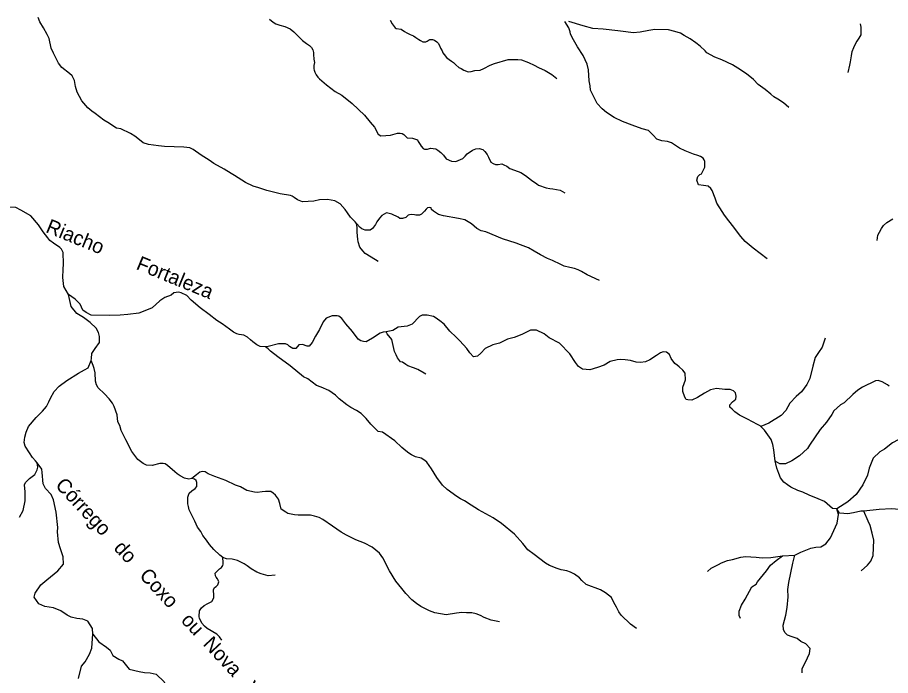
# Model space of a CAD drawing. Extents: x 717.8 to 772.7, y 8672.2 to 8728.
# Drawn here: x 733.27 to 745.36, y 8718.74 to 8727.85 of the extents above; entities that cross this region are included whole.
import ezdxf
from ezdxf.enums import TextEntityAlignment as Align

# ---------------------------------------------------------------- set-up
doc = ezdxf.new("R2010")
doc.units = 0
doc.header["$LTSCALE"] = 0.08
doc.linetypes.add('LONG_DASHED', pattern=[7.5, 6, -1.5])
doc.layers.add('61', color=7, linetype='Continuous')
doc.layers.add('9', color=7, linetype='LONG_DASHED', lineweight=25)

msp = doc.modelspace()

# ---------------------------------------------------------------- linework, layer by layer
at = {"layer": '9'}
for p, q in [((738.4321, 8727.8129), (738.462, 8727.7588)), ((743.8674, 8720.3918), (744.0397, 8720.4031))]:
    msp.add_line(p, q, dxfattribs=at)
for points in [[(737.9695, 8724.9957), (737.9482, 8725.0169), (737.885, 8725.0835), (737.8439, 8725.1443), (737.8126, 8725.192), (737.7401, 8725.2678), (737.6689, 8725.3118), (737.567, 8725.3298), (737.4566, 8725.3222), (737.3782, 8725.3061), (737.2182, 8725.2979), (737.1508, 8725.3221), (737.1055, 8725.3559), (737.0754, 8725.3727), (737.0554, 8725.3822), (736.91, 8725.4073), (736.7243, 8725.4523), (736.6139, 8725.4875), (736.5356, 8725.5139), (736.4314, 8725.5614), (736.2793, 8725.6596), (736.2341, 8725.6896), (736.1335, 8725.7497), (735.993, 8725.8287), (735.9293, 8725.8715), (735.8152, 8725.9428), (735.7068, 8726.0199), (735.6588, 8726.0425), (735.5783, 8726.0535), (735.3079, 8726.061), (735.2274, 8726.0705), (735.155, 8726.0821), (735.0896, 8726.0896), (735.0131, 8726.1134), (734.9419, 8726.173), (734.9002, 8726.2037), (734.8372, 8726.2428), (734.7058, 8726.3082), (734.6444, 8726.3175), (734.5245, 8726.3945), (734.4678, 8726.4283), (734.3509, 8726.517), (734.3017, 8726.55), (734.2478, 8726.5986), (734.1656, 8726.6926), (734.1007, 8726.8137), (734.077, 8726.8954), (734.0634, 8726.974), (734.0287, 8727.0409), (733.9942, 8727.0731), (733.8894, 8727.1578), (733.8407, 8727.218), (733.773, 8727.3538), (733.7412, 8727.4227), (733.714, 8727.5577), (733.6826, 8727.6141), (733.6351, 8727.705), (733.5819, 8727.7902), (733.5604, 8727.8492)], [(736.7653, 8727.8257), (736.8126, 8727.7819), (736.8493, 8727.7589), (736.9078, 8727.7417), (736.9741, 8727.7222), (737.0486, 8727.6909), (737.0982, 8727.648), (737.2215, 8727.5289)], [(738.462, 8727.7588), (738.5015, 8727.7078), (738.518, 8727.6957), (738.5874, 8727.6855), (738.6313, 8727.6541), (738.664, 8727.6384), (738.7115, 8727.6142), (738.7578, 8727.5925), (738.7905, 8727.5719), (738.8293, 8727.5442), (738.8554, 8727.5296), (738.8879, 8727.5105), (738.929, 8727.5095), (738.9483, 8727.5218), (738.9751, 8727.541), (738.9851, 8727.5428)], [(743.6572, 8724.5082), (743.4593, 8724.652), (743.3516, 8724.7475), (743.2897, 8724.8172), (743.2452, 8724.874), (743.195, 8724.9443), (743.1246, 8725.0317), (743.0628, 8725.1129), (743.0331, 8725.1626), (742.957, 8725.2755), (742.9331, 8725.3482), (742.8925, 8725.454), (742.8738, 8725.4798), (742.8358, 8725.5134), (742.7719, 8725.5216), (742.7026, 8725.5325), (742.6804, 8725.5971), (742.6971, 8725.6487), (742.7236, 8725.6726), (742.7455, 8725.6835), (742.7917, 8725.7782), (742.7921, 8725.8528), (742.7843, 8725.8795), (742.7702, 8725.8992), (742.7331, 8725.9221), (742.6946, 8725.9398), (742.6346, 8725.954), (742.5181, 8726.0009), (742.4391, 8726.0378), (742.33, 8726.1137), (742.2769, 8726.1295), (742.1957, 8726.14), (742.1293, 8726.1616), (742.0777, 8726.217), (742.0113, 8726.2828), (741.9244, 8726.3067), (741.7863, 8726.3583), (741.652, 8726.4073), (741.5347, 8726.4656), (741.4324, 8726.5339), (741.3686, 8726.5845), (741.3022, 8726.6577), (741.2511, 8726.7578), (741.2085, 8726.8433), (741.2048, 8726.9023), (741.1911, 8726.9713), (741.1827, 8727.1257), (741.1642, 8727.2042), (741.1057, 8727.3222), (741.0277, 8727.4433), (740.9723, 8727.5375), (740.9326, 8727.6158), (740.9276, 8727.6488), (740.9087, 8727.7054), (740.8522, 8727.7945)], [(743.9561, 8726.6007), (743.8791, 8726.6681), (743.8029, 8726.7154), (743.7468, 8726.7491), (743.7067, 8726.7868), (743.6256, 8726.8495), (743.5303, 8726.9216), (743.4643, 8726.9898), (743.3673, 8727.0685), (743.2478, 8727.1447), (743.1748, 8727.1929), (743.028, 8727.2611), (742.9285, 8727.2972), (742.8202, 8727.3582), (742.7978, 8727.3879), (742.729, 8727.4505), (742.6672, 8727.4994), (742.5878, 8727.5548), (742.5059, 8727.6014), (742.4554, 8727.6311), (742.3784, 8727.656), (742.291, 8727.6792), (742.0984, 8727.6817), (742.015, 8727.6677), (741.8946, 8727.6439), (741.7983, 8727.6375), (741.6957, 8727.6479), (741.5874, 8727.6656), (741.382, 8727.6872), (741.2395, 8727.6985), (741.1084, 8727.7312), (740.9085, 8727.7939)], [(744.7759, 8727.086), (744.7988, 8727.1891), (744.8077, 8727.2344), (744.8213, 8727.316), (744.8338, 8727.3797), (744.8563, 8727.4328), (744.8881, 8727.5006), (744.9026, 8727.5202), (744.9298, 8727.561), (744.9591, 8727.6079), (744.9591, 8727.716), (744.9475, 8727.7626)], [(737.2215, 8727.5289), (737.2745, 8727.4896), (737.3157, 8727.4593), (737.3447, 8727.4338), (737.3654, 8727.3999), (737.3716, 8727.3636), (737.3741, 8727.3285), (737.3778, 8727.2813), (737.3793, 8727.272)], [(738.9851, 8727.5428), (739.021, 8727.5438), (739.05, 8727.5341), (739.0802, 8727.5136), (739.0984, 8727.4954), (739.1167, 8727.4615), (739.1313, 8727.4239), (739.1539, 8727.3875), (739.1647, 8727.3595), (739.1838, 8727.3347), (739.2162, 8727.2967), (739.2537, 8727.2677), (739.2852, 8727.2435), (739.3107, 8727.2241), (739.3433, 8727.1938), (739.3831, 8727.1583), (739.416, 8727.1418), (739.4547, 8727.1188), (739.5167, 8727.0972)], [(737.3793, 8727.272), (737.3853, 8727.2243), (737.3793, 8727.1831), (737.3782, 8727.1371), (737.3807, 8727.1192)], [(739.5167, 8727.0972), (739.5556, 8727.0991), (739.609, 8727.1169), (739.6803, 8727.1208), (739.7319, 8727.1444), (739.8173, 8727.1896), (739.8784, 8727.2106), (740.0681, 8727.2673), (740.2005, 8727.2673), (740.2533, 8727.2609), (740.3507, 8727.2252), (740.4271, 8727.1908), (740.4863, 8727.1577), (740.5786, 8727.1138), (740.6716, 8727.0603), (740.7441, 8727.003)], [(737.3807, 8727.1192), (737.3929, 8727.0899), (737.3959, 8727.0833)], [(737.3959, 8727.0833), (737.4075, 8727.0535), (737.4331, 8727.0208), (737.4564, 8727.0013)], [(737.4564, 8727.0013), (737.5521, 8726.9141), (737.671, 8726.8241), (737.7673, 8726.7714), (737.9101, 8726.6575), (738.0796, 8726.4979), (738.1579, 8726.3992), (738.2159, 8726.3296), (738.267, 8726.2308), (738.305, 8726.2119), (738.3761, 8726.2166), (738.4378, 8726.2213), (738.5359, 8726.2454), (738.5746, 8726.2483), (738.6026, 8726.2445), (738.6258, 8726.23), (738.6693, 8726.1845), (738.7457, 8726.1797), (738.8141, 8726.1526), (738.8222, 8726.1313), (738.8508, 8726.0907), (738.865, 8726.0649), (738.8933, 8726.0365), (738.9098, 8726.0259), (738.9505, 8726.027), (738.9939, 8726.0384), (739.0645, 8726.0297), (739.0928, 8726.0128), (739.1369, 8725.9787), (739.1749, 8725.9408), (739.2113, 8725.8923), (739.2819, 8725.8585), (739.3447, 8725.8556), (739.4405, 8725.8982), (739.4743, 8725.9291), (739.5021, 8725.9599), (739.5729, 8726.0113), (739.6193, 8726.0297), (739.6667, 8726.0364), (739.7199, 8726.019), (739.7431, 8725.9919), (739.7789, 8725.9533), (739.7982, 8725.9136), (739.8301, 8725.8469), (739.8601, 8725.8246), (739.8949, 8725.813), (739.9306, 8725.815), (739.98, 8725.8208), (740.0098, 8725.8082), (740.0485, 8725.7908), (740.093, 8725.7589), (740.1568, 8725.7337), (740.2429, 8725.7024), (740.3076, 8725.6602), (740.3908, 8725.5945), (740.4632, 8725.5455), (740.487, 8725.5265), (740.5941, 8725.4891), (740.6434, 8725.4785), (740.6862, 8725.4737), (740.7871, 8725.4581), (740.8509, 8725.4213)], [(733.9818, 8724.0121), (733.9155, 8724.1229), (733.8999, 8724.2479), (733.904, 8724.3603), (733.9087, 8724.4377), (733.9038, 8724.5924), (733.8842, 8724.6408), (733.8599, 8724.665), (733.7704, 8724.7214), (733.7217, 8724.7601), (733.6926, 8724.7988), (733.6293, 8724.881), (733.563, 8724.9779), (733.4599, 8725.0998), (733.318, 8725.181), (733.251, 8725.2182), (733.1676, 8725.221), (733.0707, 8725.2174), (732.9591, 8725.2348)], [(741.3339, 8724.2064), (741.1631, 8724.284), (741.0856, 8724.3294), (741.0387, 8724.3538), (740.9883, 8724.3717), (740.924, 8724.3879), (740.8447, 8724.4053), (740.7966, 8724.4263), (740.6826, 8724.4836), (740.6142, 8724.5091), (740.517, 8724.5641), (740.4301, 8724.6131), (740.3479, 8724.6583), (740.2402, 8724.6988), (740.1777, 8724.7255), (739.99, 8724.7848), (739.7601, 8724.8815), (739.6952, 8724.8931), (739.6356, 8724.9274), (739.5607, 8724.9904), (739.4678, 8725.0445), (739.3823, 8725.0667), (739.1745, 8725.103), (739.1045, 8725.1198), (739.0327, 8725.1644), (739.0089, 8725.1916), (739.0037, 8725.2108), (738.977, 8725.2166), (738.9496, 8725.2124), (738.9319, 8725.1934), (738.9075, 8725.1645), (738.8693, 8725.1251), (738.8421, 8725.1112), (738.7912, 8725.1106), (738.7726, 8725.1141), (738.735, 8725.1193), (738.7026, 8725.1175), (738.6843, 8725.1122), (738.6693, 8725.0972), (738.6493, 8725.0772), (738.6042, 8725.067), (738.5692, 8725.067), (738.5441, 8725.0821), (738.4565, 8725.1228), (738.3838, 8725.1421), (738.321, 8725.1049), (738.2846, 8725.0707), (738.2498, 8725.0197), (738.2301, 8724.9827), (738.1913, 8724.9276), (738.1554, 8724.9045), (738.0883, 8724.9033), (738.0414, 8724.9213), (738.0188, 8724.941), (737.9695, 8724.9957)], [(745.1774, 8724.7611), (745.1878, 8724.836), (745.2103, 8724.8766), (745.2369, 8724.9262), (745.265, 8724.9674), (745.3121, 8725.01), (745.3933, 8725.0627)], [(738.2675, 8724.4694), (738.1696, 8724.5281), (738.0888, 8724.582), (738.0555, 8724.6188), (738.0154, 8724.6689), (737.9922, 8724.7423), (737.9873, 8724.7803), (737.9819, 8724.8217), (737.9794, 8724.8801), (737.976, 8724.9429), (737.9695, 8724.9957)], [(736.706, 8723.2866), (736.6351, 8723.2945), (736.5865, 8723.315), (736.5319, 8723.3566), (736.5011, 8723.3853), (736.4584, 8723.4215), (736.4092, 8723.4513), (736.3434, 8723.4601), (736.3103, 8723.4664), (736.2649, 8723.4924), (736.2071, 8723.5324), (736.1077, 8723.607), (736.0325, 8723.6545), (735.9264, 8723.7333), (735.8038, 8723.8297), (735.6771, 8723.9349), (735.6189, 8723.998), (735.5398, 8724.0348), (735.5028, 8724.0453), (735.4394, 8724.0349), (735.4024, 8724.0034), (735.3136, 8723.9701), (735.2433, 8723.9236), (735.1407, 8723.8295), (735.0379, 8723.7879), (734.9559, 8723.7559), (734.8024, 8723.7364), (734.6964, 8723.7256), (734.5483, 8723.7202), (734.2922, 8723.7278), (734.224, 8723.7621), (734.1799, 8723.7971), (734.1399, 8723.8803), (734.0718, 8723.9495), (733.9818, 8724.0121)], [(734.296, 8723.0997), (734.2972, 8723.1278), (734.3021, 8723.1955), (734.3508, 8723.2632), (734.4078, 8723.3466), (734.4092, 8723.4296), (734.3969, 8723.4866), (734.3645, 8723.5443), (734.2787, 8723.6236), (734.1861, 8723.693), (734.0956, 8723.7484), (734.0167, 8723.8446), (733.9965, 8723.9299), (733.9818, 8724.0121)], [(738.3788, 8723.4975), (738.3359, 8723.4918), (738.2973, 8723.4753), (738.1903, 8723.4077), (738.1018, 8723.3593), (738.0644, 8723.3613), (738.0291, 8723.3723), (737.9916, 8723.3943), (737.9121, 8723.5002), (737.8194, 8723.6061), (737.7644, 8723.6786), (737.7252, 8723.7104), (737.7008, 8723.7161), (737.6326, 8723.7189), (737.5477, 8723.6855), (737.508, 8723.6325), (737.455, 8723.5265), (737.427, 8723.4803), (737.4015, 8723.4359), (737.3564, 8723.3468), (737.3129, 8723.2962), (737.286, 8723.2956), (737.2209, 8723.3201), (737.1699, 8723.3145), (737.1257, 8723.2665), (737.0865, 8723.2662), (737.0405, 8723.2917), (737.0152, 8723.3162), (736.9857, 8723.3284), (736.8884, 8723.33), (736.7452, 8723.2903), (736.706, 8723.2866)], [(743.5687, 8722.1854), (743.5591, 8722.1916), (743.5207, 8722.212), (743.381, 8722.2849), (743.3386, 8722.3093), (743.2741, 8722.3422), (743.2065, 8722.3868), (743.1687, 8722.4265), (743.1403, 8722.4536), (743.1369, 8722.4845), (743.1728, 8722.5283), (743.2213, 8722.5628), (743.2265, 8722.6058), (743.2182, 8722.6519), (743.1877, 8722.6793), (743.1447, 8722.6958), (743.068, 8722.6973), (742.953, 8722.7106), (742.8684, 8722.6921), (742.7889, 8722.6457), (742.6886, 8722.5862), (742.6097, 8722.551), (742.5568, 8722.5531), (742.5354, 8722.5596), (742.5127, 8722.5901), (742.4869, 8722.6715), (742.4871, 8722.7296), (742.525, 8722.8294), (742.5205, 8722.9218), (742.4862, 8722.9651), (742.4349, 8723.0087), (742.4101, 8723.0317), (742.3779, 8723.0566), (742.3264, 8723.1283), (742.3007, 8723.1826), (742.2593, 8723.2148), (742.2152, 8723.2194), (742.1775, 8723.2065), (742.1204, 8723.1697), (742.0322, 8723.1081), (741.9706, 8723.0823), (741.9016, 8723.0704), (741.8427, 8723.0768), (741.7646, 8723.097), (741.6892, 8723.1099), (741.6239, 8723.1115), (741.5757, 8723.1097), (741.4829, 8723.0832), (741.3986, 8723.0324), (741.3067, 8723.0011), (741.1973, 8722.9689), (741.097, 8722.9772), (741.0428, 8723.0177), (741.0027, 8723.0709), (740.9223, 8723.1888), (740.7798, 8723.3369), (740.6373, 8723.4142), (740.5683, 8723.4675), (740.4626, 8723.52), (740.3771, 8723.5181), (740.2575, 8723.4583), (740.1536, 8723.4187), (740.058, 8723.393), (739.9477, 8723.3387), (739.8576, 8723.3154), (739.7481, 8723.2651), (739.6912, 8723.1986), (739.6443, 8723.1572), (739.5863, 8723.148), (739.5387, 8723.2032), (739.498, 8723.2661), (739.3989, 8723.3713), (739.3463, 8723.4203), (739.2619, 8723.5035), (739.1823, 8723.6015), (739.121, 8723.6478), (739.0594, 8723.6949), (739.0337, 8723.7095), (738.9472, 8723.728), (738.8792, 8723.7251), (738.8406, 8723.7086), (738.7376, 8723.6009), (738.6705, 8723.5761), (738.5463, 8723.5623), (738.4702, 8723.5159), (738.3788, 8723.4975)], [(738.929, 8722.9101), (738.9029, 8722.9209), (738.8171, 8722.972), (738.7569, 8722.997), (738.6791, 8723.0266), (738.6501, 8723.0414), (738.6051, 8723.0742), (738.5784, 8723.0805), (738.5353, 8723.1333), (738.5165, 8723.1748), (738.4966, 8723.2225), (738.458, 8723.3909), (738.3905, 8723.4656), (738.3788, 8723.4975)], [(744.459, 8723.4087), (744.4174, 8723.2851), (744.3682, 8723.2083), (744.3197, 8723.1421), (744.2859, 8723.0211), (744.2437, 8722.8497), (744.2048, 8722.7668), (744.13, 8722.6624), (744.0566, 8722.6007), (743.9711, 8722.509), (743.9142, 8722.4068), (743.8509, 8722.3371), (743.6804, 8722.2306), (743.5687, 8722.1854)], [(741.8449, 8719.3877), (741.7616, 8719.4476), (741.6321, 8719.5707), (741.5988, 8719.616), (741.569, 8719.6809), (741.5314, 8719.7454), (741.4989, 8719.8152), (741.4173, 8719.881), (741.3467, 8719.9225), (741.1503, 8719.9984), (741.0903, 8720.0525), (741.0544, 8720.0875), (740.9886, 8720.1384), (740.93, 8720.1692), (740.8803, 8720.185), (740.8016, 8720.2), (740.7482, 8720.2188), (740.6392, 8720.2581), (740.5868, 8720.2933), (740.4274, 8720.4125), (740.3428, 8720.4788), (740.2702, 8720.5634), (740.1567, 8720.6947), (739.9779, 8720.84), (739.8615, 8720.9182), (739.6589, 8721.0302), (739.5581, 8721.096), (739.4651, 8721.1567), (739.4074, 8721.184), (739.3579, 8721.2169), (739.2215, 8721.3114), (739.1578, 8721.3734), (739.0805, 8721.4773), (739.0052, 8721.5999), (738.9401, 8721.6883), (738.915, 8721.7145), (738.8637, 8721.7444), (738.7866, 8721.7631), (738.7319, 8721.7909), (738.6944, 8721.8143), (738.6499, 8721.8456), (738.5961, 8721.8921), (738.5002, 8721.988), (738.3276, 8722.1043), (738.2695, 8722.1154), (738.2301, 8722.1531), (738.1677, 8722.2172), (738.1036, 8722.2952), (738.0335, 8722.3649), (737.9677, 8722.4038), (737.889, 8722.4466), (737.8343, 8722.4867), (737.7285, 8722.5697), (737.6762, 8722.6193), (737.5839, 8722.6817), (737.4796, 8722.7313), (737.4121, 8722.7518), (737.296, 8722.8455), (737.2328, 8722.8717), (737.0487, 8723.0241), (736.8803, 8723.1501), (736.7751, 8723.2289), (736.7436, 8723.2604), (736.706, 8723.2866)], [(733.5469, 8721.6799), (733.5216, 8721.7099), (733.4832, 8721.7553), (733.442, 8721.8179), (733.3809, 8721.9131), (733.3681, 8721.9614), (733.3752, 8722.0353), (733.3951, 8722.1077), (733.425, 8722.1845), (733.5331, 8722.3082), (733.6207, 8722.3951), (733.6737, 8722.4602), (733.7078, 8722.5242), (733.7328, 8722.5771), (733.7803, 8722.6691), (733.8497, 8722.7414), (733.9567, 8722.8235), (734.1171, 8722.9249), (734.1998, 8722.9684), (734.2523, 8722.9981), (734.296, 8723.0997)], [(735.6887, 8721.4621), (735.6456, 8721.4573), (735.5854, 8721.4682), (735.526, 8721.5008), (735.4861, 8721.5276), (735.4506, 8721.5573), (735.35, 8721.6429), (735.3174, 8721.6662), (735.2913, 8721.6727), (735.2436, 8721.6726), (735.1391, 8721.6422), (735.0615, 8721.648), (735.0144, 8721.6712), (734.9383, 8721.7278), (734.8557, 8721.8381), (734.7723, 8721.9998), (734.7071, 8722.1288), (734.6897, 8722.1977), (734.6651, 8722.247), (734.652, 8722.3442), (734.6105, 8722.4624), (734.5881, 8722.5071), (734.5433, 8722.5697), (734.4805, 8722.6367), (734.3895, 8722.7221), (734.3678, 8722.7627), (734.3547, 8722.812), (734.3489, 8722.9266), (734.3338, 8722.9899), (734.3236, 8723.03), (734.296, 8723.0997)], [(745.3434, 8722.7426), (745.323, 8722.7613), (745.2476, 8722.8027), (745.1938, 8722.8204), (745.1534, 8722.8188), (744.9761, 8722.7279), (744.9093, 8722.6884), (744.8392, 8722.629), (744.7209, 8722.514), (744.6706, 8722.4837), (744.5801, 8722.4003), (744.5519, 8722.3503), (744.4779, 8722.2433), (744.387, 8722.1437), (744.2411, 8721.9253), (744.2114, 8721.8791), (744.1033, 8721.7796), (743.9981, 8721.7068), (743.9067, 8721.6667), (743.8319, 8721.668), (743.7681, 8721.7067)], [(746.124, 8722.2868), (746.0491, 8722.2161), (745.9355, 8722.1432), (745.8442, 8722.0964), (745.6584, 8722.0798), (745.5382, 8722.0381), (745.3923, 8721.9573), (745.278, 8721.8707), (745.2138, 8721.8353), (745.1248, 8721.7469), (745.0681, 8721.6093), (745.0438, 8721.5121), (744.979, 8721.3745), (744.8899, 8721.245), (744.7716, 8721.1422), (744.6195, 8721.0435)], [(743.7681, 8721.7067), (743.7492, 8721.8631), (743.7356, 8721.9359), (743.7108, 8722.0063), (743.6201, 8722.1336), (743.5687, 8722.1854)], [(733.3013, 8720.9295), (733.3522, 8721.0211), (733.3805, 8721.1561), (733.3813, 8721.2789), (733.3716, 8721.3756), (733.3862, 8721.4093), (733.4155, 8721.4432), (733.4398, 8721.4625), (733.5127, 8721.5204), (733.5468, 8721.5833), (733.5566, 8721.6219), (733.5469, 8721.6799)], [(734.3164, 8719.3081), (734.3129, 8719.3849), (734.248, 8719.4897), (734.1801, 8719.5162), (734.095, 8719.5247), (734.0157, 8719.5436), (733.961, 8719.5738), (733.8732, 8719.6295), (733.7741, 8719.671), (733.6542, 8719.6899), (733.5674, 8719.7277), (733.506, 8719.8202), (733.5164, 8719.8741), (733.5953, 8719.9923), (733.6786, 8720.0607), (733.8335, 8720.1836), (733.9128, 8720.279), (733.9072, 8720.38), (733.8712, 8720.4895), (733.84, 8720.5783), (733.8287, 8720.7246), (733.8317, 8720.7859), (733.811, 8721), (733.7732, 8721.1694), (733.7411, 8721.2449), (733.6609, 8721.3242), (733.6278, 8721.3884), (733.6171, 8721.5457), (733.6102, 8721.594), (733.5469, 8721.6799)], [(744.6195, 8721.0435), (744.5617, 8721.0502), (744.4484, 8721.148), (744.3626, 8721.1824), (744.2386, 8721.2313), (744.1472, 8721.2745), (744.0778, 8721.3), (743.985, 8721.3433), (743.9369, 8721.3744), (743.8866, 8721.412), (743.8384, 8721.4758), (743.8155, 8721.5344), (743.7907, 8721.6095), (743.7765, 8721.6665), (743.7681, 8721.7067)], [(739.9463, 8719.4791), (739.8325, 8719.5024), (739.7361, 8719.5413), (739.6834, 8719.5668), (739.6271, 8719.5906), (739.5655, 8719.6023), (739.4923, 8719.6052), (739.4284, 8719.6098), (739.3542, 8719.5988), (739.2118, 8719.575), (739.0545, 8719.6052), (738.9796, 8719.6308), (738.8571, 8719.6917), (738.7996, 8719.7347), (738.7328, 8719.7858), (738.6504, 8719.8724), (738.5938, 8719.9431), (738.5129, 8720.042), (738.424, 8720.185), (738.3324, 8720.3665), (738.2872, 8720.4297), (738.1846, 8720.5157), (738.0795, 8720.5685), (737.96, 8720.6132), (737.8281, 8720.6801), (737.7573, 8720.7223), (737.6379, 8720.8062), (737.5032, 8720.8957), (737.4504, 8720.9241), (737.3842, 8720.9433), (737.3325, 8720.9544), (737.214, 8720.9573), (737.1606, 8720.9573), (737.1084, 8720.9613), (737.0172, 8720.9805), (736.9887, 8720.9968), (736.9231, 8721.0398), (736.9045, 8721.1182), (736.8888, 8721.1769), (736.8444, 8721.2357), (736.8154, 8721.2635), (736.7811, 8721.2839), (736.7073, 8721.285), (736.6626, 8721.2781), (736.5923, 8721.2723), (736.5546, 8721.2734), (736.4507, 8721.296), (736.3624, 8721.3471), (736.2939, 8721.3721), (736.1586, 8721.4372), (736.0081, 8721.4912), (735.9159, 8721.5291), (735.8717, 8721.5559), (735.8362, 8721.5595), (735.7985, 8721.5515), (735.7521, 8721.5153), (735.6887, 8721.4621)], [(736.1164, 8720.3714), (736.0755, 8720.4009), (735.9919, 8720.4824), (735.9323, 8720.5515), (735.8901, 8720.6099), (735.842, 8720.6765), (735.8126, 8720.7289), (735.7642, 8720.7926), (735.7281, 8720.8736), (735.7101, 8720.9099), (735.6519, 8721.0306), (735.6431, 8721.0753), (735.631, 8721.1145), (735.6326, 8721.2042), (735.6517, 8721.2631), (735.6881, 8721.2942), (735.7342, 8721.3263), (735.7584, 8721.3554), (735.7593, 8721.4088), (735.7478, 8721.4355), (735.7234, 8721.4536), (735.6887, 8721.4621)], [(744.0397, 8720.4031), (744.12, 8720.4451), (744.26, 8720.4992), (744.3284, 8720.5122), (744.4006, 8720.5201), (744.4683, 8720.5592), (744.5321, 8720.6412), (744.6226, 8720.8471), (744.6409, 8720.9644), (744.6195, 8721.0435)], [(744.9921, 8721.0126), (744.9534, 8721.0103), (744.8485, 8720.988), (744.7718, 8720.9745), (744.7162, 8720.978), (744.6565, 8720.9864), (744.6195, 8721.0435)], [(745.786, 8720.8349), (745.6798, 8720.921), (745.6068, 8720.9741), (745.4873, 8721.0337), (745.378, 8721.0433), (745.2056, 8721.0367), (744.9921, 8721.0126)], [(744.959, 8720.1865), (745.0448, 8720.262), (745.0895, 8720.3202), (745.1238, 8720.3993), (745.133, 8720.6085), (745.1084, 8720.7071), (745.0805, 8720.8155), (745.0528, 8720.8724), (744.9921, 8721.0126)], [(736.1011, 8719.2256), (736.0726, 8719.2697), (736.0331, 8719.3069), (735.8991, 8719.3882), (735.8654, 8719.4189), (735.8259, 8719.4619), (735.8201, 8719.4759), (735.7922, 8719.5235), (735.7882, 8719.5514), (735.7917, 8719.6305), (735.821, 8719.6746), (735.8567, 8719.7037), (735.9105, 8719.7316), (735.9668, 8719.7624), (735.9839, 8719.7921), (735.993, 8719.8176), (735.9918, 8719.867), (735.9877, 8719.8995), (735.9901, 8719.9245), (735.9999, 8719.9565), (736.0254, 8719.9686), (736.048, 8719.9912), (736.0603, 8720.0332), (736.0505, 8720.0576), (736.0442, 8720.0738), (736.0254, 8720.0965), (736.0141, 8720.1152), (736.0127, 8720.1517), (736.0519, 8720.1941), (736.0707, 8720.2129), (736.0969, 8720.2321), (736.1149, 8720.2591), (736.1201, 8720.2765), (736.1218, 8720.3242), (736.1189, 8720.348), (736.1164, 8720.3714)], [(736.8395, 8720.1245), (736.7452, 8720.1187), (736.6457, 8720.1443), (736.5894, 8720.1693), (736.5104, 8720.2152), (736.454, 8720.2535), (736.4111, 8720.2837), (736.3663, 8720.3066), (736.3196, 8720.3288), (736.2446, 8720.3457), (736.1683, 8720.354), (736.1164, 8720.3714)], [(742.8298, 8720.1781), (742.88, 8720.2237), (742.9833, 8720.2757), (743.025, 8720.2982), (743.1077, 8720.3289), (743.1772, 8720.3417), (743.2918, 8720.376), (743.3536, 8720.3833), (743.5031, 8720.3728), (743.5843, 8720.3658), (743.7081, 8720.3705), (743.8674, 8720.3918)], [(743.2859, 8719.5241), (743.2684, 8719.5656), (743.2666, 8719.6275), (743.2987, 8719.7122), (743.3489, 8719.7929), (743.4406, 8719.9656), (743.5025, 8720.0006), (743.5216, 8720.0317), (743.6473, 8720.1874), (743.7005, 8720.2657), (743.7782, 8720.327), (743.8674, 8720.3918)], [(744.1388, 8718.773), (744.1412, 8718.8302), (744.2159, 8718.9797), (744.241, 8719.0411), (744.2486, 8719.1082), (744.1926, 8719.1727), (744.1214, 8719.209), (744.0711, 8719.2469), (744.0022, 8719.2726), (743.9363, 8719.296), (743.8995, 8719.3304), (743.8831, 8719.3725), (743.8755, 8719.4321), (743.9118, 8719.5717), (743.9332, 8719.6768), (743.9439, 8719.8279), (743.9433, 8719.929), (743.9552, 8720.0259), (744.0083, 8720.2928), (744.0397, 8720.4031)], [(734.119, 8718.6953), (734.1582, 8718.8638), (734.2118, 8718.9232), (734.2701, 8719.0329), (734.3029, 8719.113), (734.3103, 8719.2489), (734.3164, 8719.3081)], [(734.3164, 8719.3081), (734.4014, 8719.2009), (734.508, 8719.1278), (734.5546, 8719.088), (734.5917, 8719.0154), (734.6759, 8718.964), (734.7276, 8718.9382), (734.8182, 8718.8258), (734.957, 8718.7918), (735.0315, 8718.7777), (735.1127, 8718.7739), (735.1948, 8718.756), (735.3034, 8718.6493), (735.3617, 8718.5278)]]:
    msp.add_lwpolyline(points, dxfattribs=at)

# ---------------------------------------------------------------- texts
at = {"layer": '61'}
for s, rotation, p in [('Riacho       Fortaleza', 337.722, (734.7938, 8724.4126)), ('Córrego   do   Coxo   ou  Nova   Vista', 312.924, (735.2994, 8719.7352))]:
    msp.add_text(s, height=0.2, rotation=rotation, dxfattribs=at).set_placement(p, align=Align.CENTER)

doc.saveas('drawing.dxf')
